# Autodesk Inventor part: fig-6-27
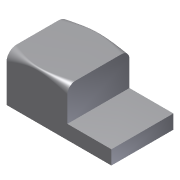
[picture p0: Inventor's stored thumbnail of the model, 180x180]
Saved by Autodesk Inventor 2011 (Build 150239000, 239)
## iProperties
Created: 2004-05
Part Number: fig-6-27
Document SubType Name: Modeling
Designer: CADCIM Technologies
Manufacturer: Standard
Standards Organization: Custom
Density: 1 g/cm^3
Author: CADCIM Technologies
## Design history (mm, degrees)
node "Sketch1"
sketch "Sketch2"
  geometry: L1 (0.098, 47.711)-(0.098, 0.049); L2 (0.098, 0.049)-(-105.483, 0.049); L3 (-105.483, 0.049)-(-105.483, 14.192); L4 (-105.483, 14.192)-(-61.139, 14.192); L5 (-61.139, 14.192)-(-61.139, 47.711); L6 (-61.139, 47.711)-(0.098, 47.711)
  constraints: 12 end point, 3 parallel, 2 perpendicular, 1 vertical
extrude "Extrusion1" new body sketch "Sketch2" stored distance "d0" = 62.5; taper "d1" = 0 deg
fillet "Fillet9" dims "d61" = 10, "d62" = 8, "d63" = 2, "d64" = 5
fillet "Fillet10" dims "d65" = 8, "d66" = 10, "d67" = 2, "d68" = 5
body "Solid1"
